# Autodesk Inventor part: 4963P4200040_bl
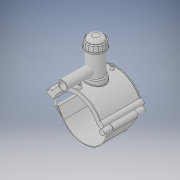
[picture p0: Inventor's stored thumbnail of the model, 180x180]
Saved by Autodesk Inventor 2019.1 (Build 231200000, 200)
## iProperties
Created: 2017-07
Part Number: 4963P4200040_bl
Material: Generic
Document SubType Name: Modeling
Designer: KIM
Density: 1 g/cm^3
Appearance: Default
Author: KIM
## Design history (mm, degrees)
derived "4963P4.ipt"
feature "Solid1::4963P4.ipt" dims "ScaleForDerivedMember" = 10
feature "Solid2::4963P4.ipt" dims "ScaleForDerivedMember" = 10
feature "Solid3::4963P4.ipt" dims "ScaleForDerivedMember" = 10
tag "TaggingFeature1"
body "Solid1"
body "Solid2"
body "Solid3"
other parameters: "d2" = 262.6 [user parameter], "d4" = 176 [user parameter], "d5" = 0 [user parameter], "d6" = 0.1 [user parameter], "d8" = 0 [user parameter], "d19" = 6 [user parameter], "d20" = 6 [user parameter], "d21" = 105.6 [user parameter], "d23" = 0 [user parameter], "d24" = 52.8 [user parameter], "d26" = 0 [user parameter], "d27" = 3 [user parameter], "d28" = 3 [user parameter], "d29" = 3 [user parameter], "d30" = 66.66667 [user parameter], "d31" = 6 [user parameter], "d32" = 0 [user parameter], "d33" = 0 [user parameter], "d34" = 0.6 [user parameter], "d40" = 120.64 [user parameter], "d43" = 0 [user parameter], "d45" = 0 [user parameter], "d47" = 221.6 [user parameter], "d70" = 15 [user parameter], "d72" = 0 [user parameter], "d73" = 6 [user parameter], "d75" = 5 [user parameter], "d76" = 0 [user parameter], "d79" = 15 [user parameter], "d80" = 70.4 [user parameter], "d82" = 5 deg [user parameter], "d84" = 4 [user parameter], "d85" = 14 [user parameter], "d86" = 0 [user parameter], "d87" = 3 [user parameter], "d88" = 0 [user parameter], "d89" = 1 [user parameter], "d90" = 1 [user parameter], "d91" = 140.8 [user parameter], "d92" = 0 [user parameter], "d93" = 0.5 [user parameter], "d94" = 105.26316 [user parameter], "d96" = 236.64 [user parameter], "d97" = 3.52 [user parameter], "d98" = 0 [user parameter], "d102" = 2 [user parameter], "d120" = 140 deg [user parameter], "d121" = 24.228 [user parameter], "d122" = 20 deg [user parameter], "d123" = 464 [user parameter], "d124" = 139.2 [user parameter], "d126" = 0 [user parameter], "d143" = 206 [user parameter], "d145" = 24.61538 [user parameter], "d149" = 3 [user parameter], "d150" = 27.07692 [user parameter], "d153" = 176 [user parameter], "d154" = 0 [user parameter], "d156" = 116 [user parameter], "d157" = 160 deg [user parameter], "d159" = 6.4 [user parameter], "d161" = 3 [user parameter], "d162" = 105.6 [user parameter], "d163" = 0 [user parameter], "d168" = 113.17073 [user parameter], "d170" = 3 [user parameter], "d172" = 0 [user parameter], "d173" = 1 [user parameter], "d176" = 20 deg [user parameter], "d177" = 14 [user parameter], "d178" = 32 [user parameter], "d180" = 0 [user parameter], "d183" = 12.8 [user parameter], "d184" = 11.2 [user parameter], "d185" = 57.2 [user parameter], "d186" = 57.2 [user parameter], "d187" = 116 [user parameter], "d188" = 9.6 [user parameter], "d189" = 14 [user parameter], "d190" = 0 [user parameter], "d191" = 174 [user parameter], "d193" = 6.4 [user parameter], "d194" = 6.16 [user parameter], "d195" = 90 deg [user parameter], "d197" = 0 [user parameter], "d199" = 0 [user parameter], "d200" = 16 [user parameter], "d202" = 0 [user parameter], "d203" = 177 [user parameter], "d204" = 76 [user parameter], "d205" = 56 [user parameter], "d206" = 68 [user parameter], "d207" = 132.75 [user parameter], "d208" = 138.06 [user parameter], "d209" = 164.61 [user parameter], "d210" = 68.8 [user parameter], "d212" = 64 [user parameter], "d213" = 36 [user parameter], "d216" = 0 [user parameter], "d219" = 4 [user parameter], "d224" = 0 [user parameter], "d227" = 32 [user parameter], "d228" = 142 [user parameter], "d230" = 4 [user parameter], "B_" = 202 [user parameter], "L_" = 176 [user parameter], "d_t" = 6 [user parameter], "H_2" = 177 [user parameter], "H_" = 142 [user parameter], "d1" = 232 [user parameter], "d148" = 3 [user parameter], "d160" = 3 [user parameter], "d169" = 3 [user parameter], "d192" = 6.4 [user parameter]
